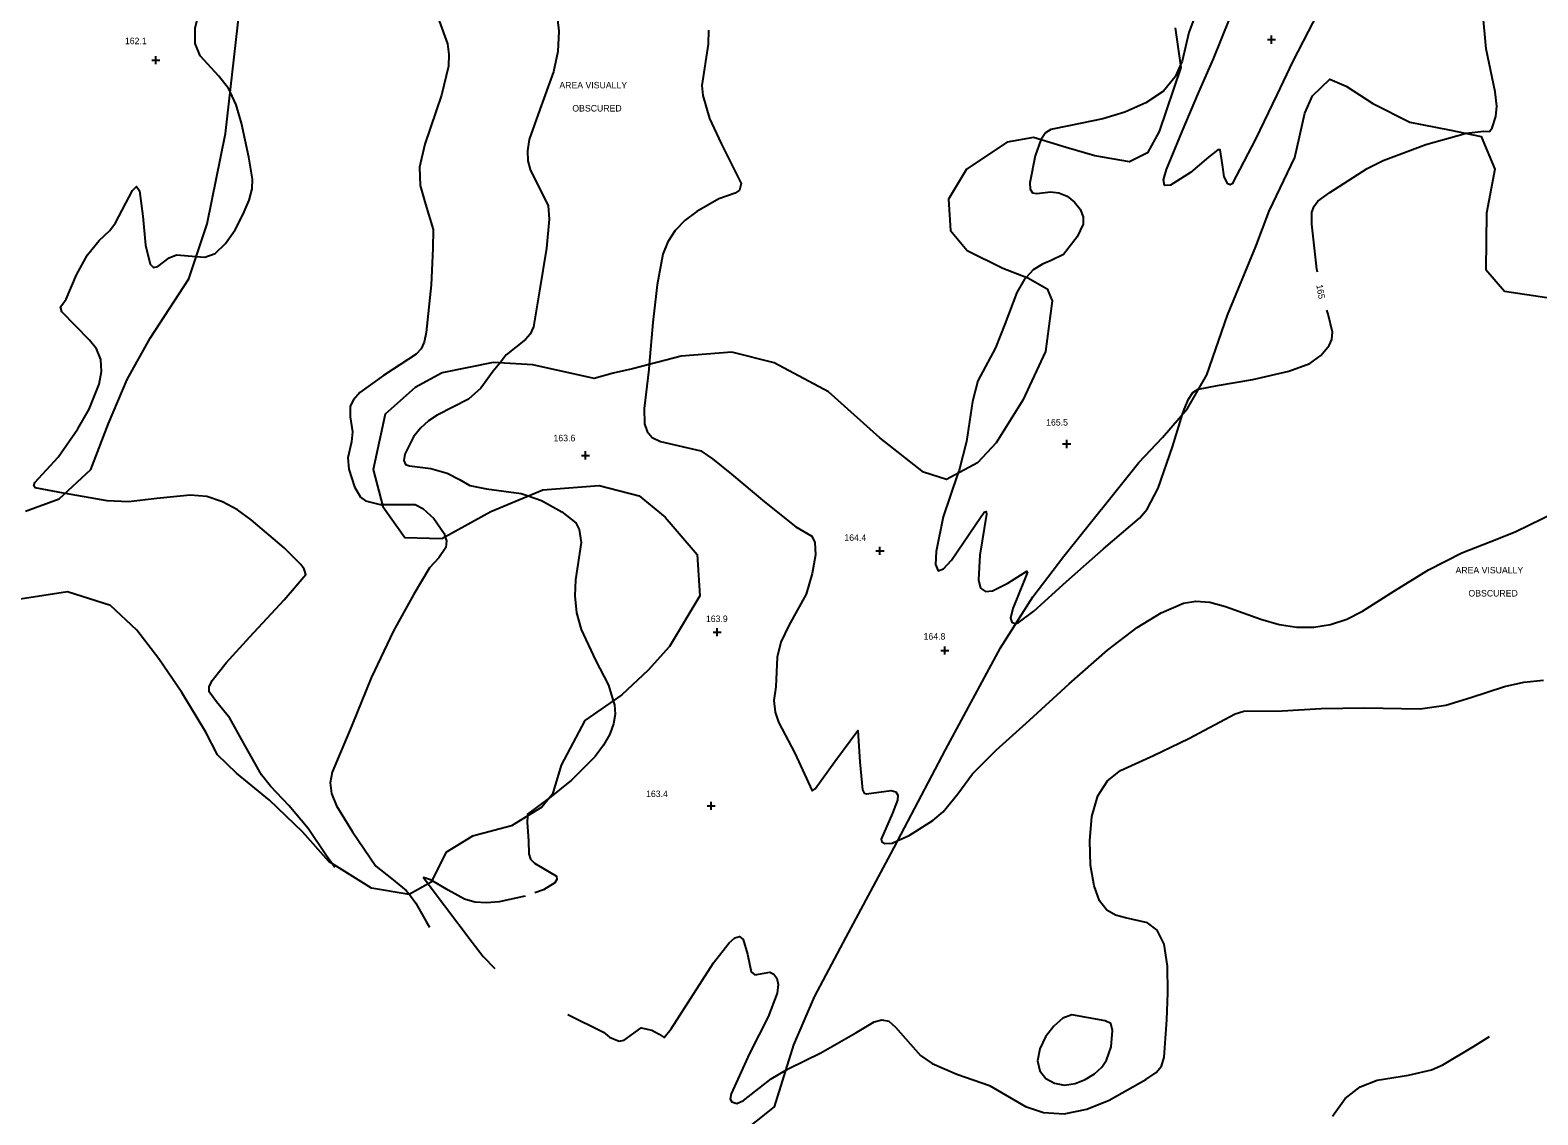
# Model space of a CAD drawing. Extents: x 1467615 to 2003689, y 770235 to 1108726.
# Drawn here: x 1998713.9 to 1999177.2, y 774676.6 to 775010.1 of the extents above; entities that cross this region are included whole.
import ezdxf

# ---------------------------------------------------------------- set-up
doc = ezdxf.new("R2010")
doc.units = 0
for name, color, linetype in [('RD_DTM_Major1', 7, 'Continuous'), ('RD_DTM_Major1_Lbl', 7, 'Continuous'), ('RD_DTM_Major2', 7, 'Continuous'), ('RD_DTM_Minor1', 7, 'Continuous'), ('RD_DTM_Minor2', 7, 'Continuous'), ('RD_DTM_Obscure', 7, 'Continuous'), ('RD_DTM_Spot_Elev', 7, 'Continuous'), ('RD_TX_Misc1', 7, 'Continuous')]:
    doc.layers.add(name, color=color, linetype=linetype)

msp = doc.modelspace()

# ---------------------------------------------------------------- linework, layer by layer
at = {"layer": 'RD_DTM_Major1'}
for points in [[(1999093.32, 775063.9), (1999090.35, 775061.66), (1999087.9, 775058.69), (1999085.26, 775053.24), (1999081.17, 775042.14), (1999078.45, 775030.23), (1999075.47, 775020.42), (1999073.98, 775017.94), (1999072.05, 775015.06), (1999069.94, 775009.38), (1999067.83, 775000.5), (1999067.36, 774999.45)], [(1999113.39, 775022.77), (1999106.54, 775009.68), (1999101.89, 775000.49), (1999096.94, 774990.22), (1999090.36, 774976.51), (1999083.27, 774962.77), (1999082.58, 774962.47), (1999081.93, 774962.81), (1999080.79, 774965), (1999080.22, 774968.68), (1999079.55, 774973.22), (1999078.86, 774973.28), (1999076, 774970.97), (1999070.45, 774966.32), (1999064.25, 774962.39), (1999062.43, 774962.28), (1999062.12, 774964.06), (1999063.01, 774967.27), (1999067.89, 774978.92), (1999072.98, 774990.95), (1999077.52, 775001.22), (1999082.39, 775013.49)], [(1999155.09, 774978.36), (1999160.58, 774979.05), (1999162.26, 774978.93), (1999163.14, 774980.07), (1999164.25, 774983.54), (1999164.6, 774986.68), (1999164.04, 774991.15), (1999161.25, 775004.33), (1999160.29, 775015.45)], [(1999024.48, 774976.37), (1999022.66, 774971.43), (1999021.07, 774963.15), (1999021.19, 774961.21), (1999021.87, 774960.06), (1999023.23, 774959.81), (1999027.44, 774960.33), (1999029.95, 774960.1), (1999032.48, 774959), (1999034.76, 774957.2), (1999036.52, 774954.98), (1999037.48, 774952.64), (1999037.46, 774950.42), (1999035.56, 774946.55), (1999031.37, 774941.09), (1999027.58, 774939.27), (1999024.93, 774938.14), (1999022.12, 774936.34), (1999020.02, 774934.13)], [(1999068.01, 774892.03), (1999068.45, 774893.42), (1999069.79, 774896.65), (1999071.11, 774898.66), (1999072.76, 774899.71), (1999072.91, 774899.74)], [(1998998.97, 774873.79), (1998994.38, 774860.48), (1998992.24, 774849.79), (1998992.1, 774845.79), (1998992.84, 774843.83), (1998994.57, 774844.48), (1998996.97, 774847.13), (1999004.34, 774858.03), (1999007.04, 774861.85), (1999007.63, 774862.13), (1999007.74, 774861.22), (1999005.66, 774848.67), (1999005.25, 774841.03), (1999005.94, 774838.55), (1999007.44, 774837.52), (1999009.54, 774837.7), (1999014.31, 774840.04), (1999020.14, 774843.77), (1999020.32, 774843.38), (1999019.36, 774840.83), (1999015.78, 774832.21), (1999015.1, 774829.24), (1999015.56, 774828.06), (1999016.49, 774827.6), (1999016.78, 774827.68)]]:
    msp.add_lwpolyline(points, dxfattribs=at)
at = {"layer": 'RD_DTM_Major2'}
for points in [[(1999067.36, 774999.45), (1999065.7, 774995.72), (1999062.1, 774991.31), (1999056.72, 774987.68), (1999050.21, 774984.84), (1999043.51, 774982.76), (1999033.01, 774980.63), (1999027.53, 774979.56), (1999025.89, 774978.5), (1999024.59, 774976.68), (1999024.48, 774976.37)], [(1999109.4, 774935.67), (1999109.26, 774936.54), (1999107.67, 774950.4), (1999107.75, 774954.15), (1999108.38, 774955.92), (1999109.54, 774957.44), (1999113.2, 774960.17), (1999124.72, 774967.58), (1999129.66, 774969.96), (1999142.75, 774974.87), (1999154.78, 774978.32), (1999155.09, 774978.36)], [(1999020.02, 774934.13), (1999019.42, 774933.5), (1999017.08, 774929.4), (1999013.34, 774919.66), (1999010.52, 774912.39), (1999005.05, 774902.28), (1999003.4, 774895.9), (1999001.63, 774883.61), (1998999.32, 774874.82), (1998998.97, 774873.79)], [(1999072.91, 774899.74), (1999078.77, 774900.77), (1999089.62, 774902.68), (1999100.65, 774905.2), (1999107.09, 774907.55), (1999110.46, 774910), (1999113.06, 774913.07), (1999113.87, 774914.98), (1999114.1, 774917.21), (1999112.69, 774922.71), (1999112.27, 774923.99)], [(1999016.78, 774827.68), (1999017.42, 774827.86), (1999022.25, 774831.47), (1999032.36, 774840.53), (1999043.71, 774850.64), (1999054.79, 774860.07), (1999057.09, 774862.8), (1999060.44, 774869.22), (1999064.88, 774882.01), (1999068.01, 774892.03)]]:
    msp.add_lwpolyline(points, dxfattribs=at)
at = {"layer": 'RD_DTM_Minor1'}
msp.add_line((1998807.45, 774752.68), (1998806.52, 774754), dxfattribs=at)
for points in [[(1998775.28, 774991.06), (1998774.8, 774992.1), (1998771.85, 774995.95), (1998766.13, 775002.21), (1998764.57, 775005.92), (1998764.52, 775010.63), (1998765.76, 775015.76), (1998767.9, 775020.49), (1998770.54, 775024.01), (1998773.35, 775025.76), (1998779.41, 775027.42)], [(1998724.59, 774867.63), (1998715.44, 774869.35), (1998714.94, 774870), (1998715.32, 774870.96), (1998722.45, 774878.8), (1998728.54, 774887.53), (1998731.98, 774893.58), (1998735.04, 774901.21), (1998735.77, 774905.14), (1998735.56, 774908.83), (1998734.21, 774912.05), (1998732.09, 774914.79), (1998723.61, 774923.51), (1998723.2, 774925.03), (1998723.92, 774925.88), (1998724.95, 774927.4), (1998728.1, 774934.88), (1998731.5, 774941.03), (1998735.04, 774945.36), (1998738.37, 774948.43), (1998740.09, 774950.81), (1998745.28, 774960.81), (1998746.58, 774961.96), (1998747.46, 774960.62), (1998748.44, 774952.9), (1998749.3, 774943.94), (1998750.76, 774938.13), (1998751.8, 774937.07), (1998753.1, 774937.44), (1998756.59, 774940.09), (1998758.85, 774940.96), (1998764.9, 774940.47)], [(1998858.16, 774907.73), (1998856.18, 774905.18), (1998852.39, 774899.98), (1998848.55, 774896.65), (1998838.89, 774891.69), (1998836.24, 774889.92), (1998833.77, 774887.72), (1998831.64, 774885.08), (1998828.95, 774879.71), (1998828.65, 774877.72), (1998829.17, 774876.58), (1998830.42, 774876.09), (1998836.96, 774875.33), (1998841.98, 774873.82), (1998845.81, 774871.89), (1998849.01, 774870.1), (1998854.07, 774869.01), (1998864.74, 774867.64), (1998866.91, 774866.89)], [(1998904.11, 774907.28), (1998903.97, 774905.76), (1998902.54, 774893.71), (1998902.67, 774889.04), (1998903.45, 774886.7), (1998905.04, 774884.81), (1998907.6, 774883.6), (1998919.94, 774880.69), (1998923.51, 774878.24), (1998929.35, 774873.53), (1998939.48, 774865.04), (1998949.1, 774857.38), (1998954.1, 774854.51), (1998954.97, 774852.53), (1998955.17, 774848.73), (1998954.18, 774843.04), (1998952.36, 774836.69), (1998947, 774827), (1998944.5, 774821.91), (1998943.44, 774817.29), (1998942.99, 774808.22), (1998942.43, 774804.01), (1998942.76, 774800.43), (1998943.81, 774797.31), (1998948.82, 774787.78), (1998954.19, 774776.21), (1998955.04, 774776.82), (1998961.1, 774785.2), (1998968.19, 774794.8), (1998968.85, 774785.15), (1998969.68, 774776.48), (1998970.11, 774775.5), (1998970.88, 774775.24), (1998978.39, 774776.27), (1998979.9, 774775.89), (1998980.53, 774774.88), (1998980.41, 774773.34), (1998978.84, 774769.38), (1998975.32, 774761.37), (1998975.58, 774760.48), (1998976.48, 774759.98), (1998978.72, 774760.14), (1998980.49, 774760.93)], [(1998822.11, 774864.24), (1998827.69, 774864.23), (1998832.16, 774864.23), (1998834.57, 774863.05), (1998837.9, 774859.94), (1998841.08, 774855.34), (1998841.39, 774854.32)], [(1998893.06, 774803.92), (1998893.47, 774802.63), (1998893.58, 774799.76), (1998893.09, 774796.77), (1998891.95, 774793.62), (1998890.09, 774790.29), (1998887.46, 774786.77), (1998880.26, 774779.52), (1998873.38, 774773.97)], [(1998866.67, 774768.45), (1998866.6, 774766.45), (1998866.96, 774760.79), (1998867.08, 774756.79), (1998867.66, 774755.17), (1998868.8, 774753.96), (1998875.55, 774749.94), (1998875.71, 774748.97), (1998875.12, 774747.93), (1998871.57, 774745.78), (1998868.99, 774744.89)], [(1998836.15, 774747.59), (1998841.21, 774740.95), (1998849.7, 774729.73), (1998853.08, 774725.3), (1998856.69, 774721.6)], [(1998865.94, 774743.85), (1998865.49, 774743.69), (1998857.94, 774742.07), (1998854.1, 774741.76), (1998850.5, 774742), (1998847.32, 774742.89), (1998842.28, 774745.63), (1998837.33, 774748.61)], [(1998830.39, 774744.32), (1998832.42, 774741.72), (1998835.7, 774735.83), (1998836.57, 774734.3)], [(1998879.12, 774707.45), (1998879.13, 774707.44), (1998890.02, 774701.96), (1998891.85, 774700.52), (1998894.9, 774699.27), (1998896.4, 774699.59), (1998901.58, 774703.32), (1998904.85, 774702.66), (1998907.18, 774701.35), (1998908.67, 774700.35), (1998910.8, 774703.03), (1998916.84, 774712.46), (1998923.86, 774723.3), (1998928.64, 774729.5), (1998930.37, 774731.03), (1998931.86, 774731.45), (1998932.97, 774730.46), (1998934.28, 774725.94), (1998935.37, 774720.53), (1998936.54, 774719.67), (1998941.15, 774720.41), (1998942.35, 774719.82), (1998943.27, 774718.6), (1998943.7, 774716.69), (1998943.43, 774714.03), (1998940.6, 774706.71), (1998934.89, 774695.41), (1998929.24, 774683.06), (1998928.96, 774681.39), (1998929.47, 774680.61), (1998930.99, 774680.06), (1998933.08, 774681.01), (1998941.56, 774687.7), (1998946.12, 774690.3)]]:
    msp.add_lwpolyline(points, dxfattribs=at)
at = {"layer": 'RD_DTM_Minor2'}
for points in [[(1998875.57, 775015.98), (1998876.32, 775009.78), (1998876.01, 775003.46), (1998874.66, 774997.2), (1998870.46, 774985.63), (1998867.25, 774976.49), (1998866.67, 774972.96), (1998866.77, 774969.93), (1998867.52, 774967.26), (1998872.99, 774956.06), (1998873.34, 774951.98), (1998872.54, 774943), (1998870.34, 774929.92), (1998868.52, 774918.9), (1998867.5, 774916.63), (1998866.04, 774914.91), (1998860.14, 774910.28), (1998858.16, 774907.73)], [(1998839.55, 775012.95), (1998842.09, 775005.86), (1998842.53, 775002.56), (1998842.38, 774999.03), (1998840.23, 774990.11), (1998835.18, 774974.98), (1998833.54, 774967.91), (1998833.75, 774962.31), (1998835.36, 774956.54), (1998837.73, 774948.73), (1998837.64, 774942.98), (1998837.04, 774931.76), (1998835.6, 774917.11), (1998834.98, 774914.1), (1998834.04, 774912.05), (1998832.48, 774910.43), (1998822.4, 774903.9), (1998815.17, 774898.64), (1998813.18, 774896.42), (1998812.24, 774894.5), (1998812.24, 774891.2), (1998812.93, 774886.56), (1998812.57, 774883.45), (1998811.47, 774878.57), (1998811.81, 774875.09), (1998813.5, 774869.67), (1998815.4, 774866.49), (1998816.95, 774865.34), (1998821.39, 774864.24), (1998822.11, 774864.24)], [(1998922.27, 775010.11), (1998922.18, 775005.78), (1998920.27, 774993.03), (1998920.53, 774990.01), (1998922.62, 774982.94), (1998926.19, 774975.21), (1998932.38, 774962.91), (1998931.85, 774960.91), (1998930.53, 774959.92), (1998925.52, 774958.19), (1998918.74, 774954.36), (1998915.14, 774951.62), (1998912.04, 774948.48), (1998909.78, 774945.02), (1998908.27, 774941.15), (1998906.51, 774931.74), (1998905.25, 774920.15), (1998904.11, 774907.28)], [(1998764.9, 774940.47), (1998767.49, 774940.25), (1998770.7, 774941.43), (1998773.9, 774944.43), (1998776.86, 774948.71), (1998779.36, 774953.46), (1998781.15, 774957.84), (1998782.06, 774961.3), (1998782.23, 774964.22), (1998781.09, 774970.99), (1998778.85, 774981.51), (1998777.13, 774987.14), (1998775.28, 774991.06)], [(1998806.52, 774754), (1998804.97, 774756.23), (1998799.29, 774764.61), (1998793.34, 774771.74), (1998787.68, 774777.62), (1998784.99, 774781.1), (1998779.89, 774790.06), (1998775.18, 774798.58), (1998771.09, 774803.6), (1998768.87, 774806.64), (1998768.91, 774808.2), (1998769.79, 774810.09), (1998774.13, 774815.52), (1998781.39, 774823.54), (1998791.94, 774834.95), (1998798.61, 774842.76), (1998798.08, 774844.4), (1998797.05, 774845.82), (1998791.89, 774850.88), (1998781.81, 774859.57), (1998777.59, 774862.58), (1998773.01, 774865.08), (1998768.12, 774866.69), (1998763, 774867.15), (1998752.8, 774866.03), (1998744.06, 774865.04), (1998737.55, 774865.38), (1998724.69, 774867.62), (1998724.59, 774867.63)], [(1998866.91, 774866.89), (1998870.95, 774865.48), (1998877.25, 774861.94), (1998881.51, 774858.59), (1998882.55, 774856.5), (1998883.16, 774852.54), (1998881.4, 774841.08), (1998881.2, 774836.15), (1998881.71, 774830.97), (1998883.14, 774825.83), (1998887.57, 774816.33), (1998891.55, 774808.67), (1998893.06, 774803.92)], [(1998980.49, 774760.93), (1998983.96, 774762.49), (1998991.21, 774767.08), (1998994.44, 774769.76), (1998998.96, 774775.29), (1999003.43, 774781.41), (1999010.71, 774788.71), (1999020.93, 774797.91), (1999033.13, 774809.05), (1999044.87, 774819.42), (1999054.04, 774826.46), (1999061.37, 774830.95), (1999068.29, 774833.94), (1999072.07, 774834.53), (1999076.33, 774834.22), (1999081.19, 774832.91), (1999092.06, 774828.95), (1999097.64, 774827.31), (1999103.08, 774826.47), (1999108.35, 774826.49), (1999113.47, 774827.35), (1999118.45, 774829.02), (1999123.32, 774831.45), (1999133.09, 774837.67), (1999143.52, 774844.11), (1999153.78, 774849.36), (1999164.53, 774853.58), (1999170.44, 774855.91), (1999182.55, 774861.83)], [(1998841.39, 774854.32), (1998841.78, 774853.04), (1998841.55, 774851.01), (1998839.41, 774847.87), (1998836.61, 774844.8), (1998831.75, 774836.65), (1998825.48, 774825.35), (1998818.7, 774810.9), (1998812.72, 774796.29), (1998806.69, 774781.9), (1998806.07, 774778.67), (1998806.49, 774775.36), (1998808.04, 774771.55), (1998812.88, 774763.57), (1998820.12, 774753.02), (1998824.9, 774749.3), (1998829.4, 774745.6), (1998830.39, 774744.32)], [(1998946.12, 774690.3), (1998946.99, 774690.79), (1998956.87, 774695.7), (1998967.59, 774701.85), (1998973.19, 774705.18), (1998975.53, 774705.83), (1998977.7, 774705.36), (1998979.79, 774703.58), (1998987.46, 774694.81), (1998991.03, 774692.38), (1998998.64, 774689.11), (1999008.64, 774685.6), (1999019.73, 774679.16), (1999025.27, 774677.32), (1999031.6, 774676.88), (1999038.52, 774678.34), (1999045.46, 774681.15), (1999056.69, 774687.45), (1999059.83, 774689.59), (1999061.51, 774691.56), (1999062.29, 774694.33), (1999063.18, 774705.82), (1999063.5, 774714.1), (1999063.31, 774722.33), (1999062.28, 774729.1), (1999060.16, 774733.39), (1999057.23, 774735.61), (1999050.47, 774737.11), (1999047.36, 774737.94), (1999044.67, 774739.56), (1999042.45, 774742.42), (1999040.77, 774746.95), (1999039.72, 774753.34), (1999039.45, 774760.8), (1999040.12, 774768.27), (1999041.91, 774774.7), (1999044.91, 774779.31), (1999048.94, 774782.48), (1999059.01, 774787.05), (1999069.9, 774792.33), (1999084.16, 774799.86), (1999086.77, 774800.67), (1999098.56, 774800.79), (1999110.57, 774801.53), (1999123.9, 774801.7), (1999141.04, 774801.43), (1999148.85, 774802.49), (1999156.55, 774804.94), (1999166.96, 774808.32), (1999172.87, 774809.63), (1999178.91, 774810.21)], [(1998873.38, 774773.97), (1998873.07, 774773.71), (1998866.69, 774769.06), (1998866.67, 774768.45)], [(1998837.33, 774748.61), (1998836.9, 774748.87), (1998834.69, 774749.51), (1998836.15, 774747.59)], [(1999031.71, 774685.75), (1999034.96, 774686.2), (1999038.09, 774687.45), (1999040.9, 774689.23), (1999043.13, 774691.3), (1999044.64, 774693.41), (1999046.03, 774697.5), (1999046.48, 774702.56), (1999045.95, 774704.65), (1999044.19, 774705.53), (1999033.97, 774707.37), (1999031.21, 774706.28), (1999028.4, 774703.9), (1999025.91, 774700.58), (1999024.12, 774696.84), (1999023.43, 774693.2), (1999024.12, 774690.13), (1999025.95, 774687.79), (1999028.6, 774686.29), (1999031.71, 774685.75)], [(1999114.1, 774676.23), (1999117.93, 774681.65), (1999122.61, 774685.22), (1999127.75, 774687.24), (1999137.44, 774688.84), (1999144.52, 774690.39), (1999147.99, 774691.92), (1999157.43, 774697.6), (1999162.33, 774700.68)]]:
    msp.add_lwpolyline(points, dxfattribs=at)
at = {"layer": 'RD_DTM_Obscure'}
for points in [[(1998712.46, 774862.18), (1998722.8, 774865.97), (1998732.5, 774874.97), (1998737.91, 774889.18), (1998743.65, 774902.62), (1998750.7, 774915.4), (1998762.65, 774933.65), (1998768.22, 774950.54), (1998773.84, 774978.33), (1998779.68, 775029.84)], [(1999065.7, 775010.77), (1999067.49, 774998.6), (1999060.79, 774978.87), (1999057.16, 774972.38), (1999051.64, 774969.63), (1999041.02, 774971.39), (1999032.17, 774974.01), (1999022.2, 774977.07), (1999014.09, 774975.63), (1999001.56, 774967.36), (1998996.05, 774958.12), (1998996.65, 774948.52), (1999001.83, 774942.3), (1999012.8, 774936.88), (1999020.48, 774933.95), (1999026.41, 774930.55), (1999027.91, 774926.83), (1999025.87, 774911.25), (1999018.88, 774896.35), (1999010.66, 774883.24), (1999004.95, 774877.07), (1998995.47, 774871.87), (1998988.33, 774874.2), (1998974.97, 774884.72), (1998959.15, 774898.83), (1998942.46, 774907.82), (1998929.47, 774911.06), (1998913.93, 774909.85), (1998898.99, 774905.94), (1998893, 774904.57), (1998887.18, 774903), (1998868.32, 774907.14), (1998856.14, 774907.84), (1998840.49, 774904.74), (1998832.21, 774900.25), (1998822.96, 774892), (1998819.3, 774875.04), (1998822.27, 774863.6), (1998828.97, 774854.05), (1998840.41, 774853.77), (1998855.4, 774862.07), (1998871.45, 774868.79), (1998888.72, 774870.08), (1998900.96, 774866.89), (1998909, 774860.31), (1998918.86, 774848.83), (1998919.66, 774836.15), (1998910.34, 774820.61), (1998903.79, 774813.33), (1998895.7, 774805.76), (1998884.33, 774797.81), (1998877.03, 774784.07), (1998874.42, 774775.23), (1998871.13, 774771.22), (1998861.81, 774765.44), (1998849.77, 774762.31), (1998841.63, 774757.24), (1998837.09, 774748.12), (1998830.36, 774744.3), (1998818.8, 774746.31), (1998805.69, 774754.53), (1998797.6, 774763.6), (1998787.45, 774773.37), (1998777.22, 774781.61), (1998771.43, 774787.3), (1998767.81, 774794.2), (1998760.49, 774806.48), (1998753.43, 774816.83), (1998746.68, 774825.63), (1998738.51, 774833.17), (1998725.38, 774837.37), (1998710.75, 774835.16)], [(1998932.01, 774670.69), (1998942.64, 774679.07), (1998948.53, 774698.07), (1998954.93, 774712.83), (1998964.61, 774731.22), (1998978.34, 774756.85), (1998995.12, 774788.8), (1999012.04, 774820.16), (1999021.94, 774835.85), (1999031.45, 774848.3), (1999054.54, 774877.18), (1999061.86, 774884.79), (1999069.45, 774893.72), (1999075.41, 774904.09), (1999081.83, 774922.47), (1999090.5, 774943.58), (1999094.58, 774954.44), (1999102.51, 774970.92), (1999105.59, 774984.52), (1999107.91, 774989.84), (1999113.28, 774994.98), (1999118.23, 774992.88), (1999126.43, 774987.52), (1999137.87, 774981.79), (1999149.89, 774979.47), (1999159.72, 774977.37), (1999163.93, 774967.37), (1999161.33, 774953.83), (1999161.19, 774936.51), (1999166.93, 774929.86), (1999179.94, 774927.86)]]:
    msp.add_lwpolyline(points, dxfattribs=at)
at = {"layer": 'RD_DTM_Spot_Elev'}
for p, q in [((1999094.08, 775007.14), (1999096.58, 775007.14)), ((1999095.33, 775005.89), (1999095.33, 775008.39)), ((1998751.25, 775000.85), (1998753.75, 775000.85)), ((1998752.5, 774999.6), (1998752.5, 775002.1)), ((1999032.38, 774881.59), (1999032.38, 774884.09)), ((1998884.54, 774878.08), (1998884.54, 774880.58)), ((1999031.13, 774882.84), (1999033.63, 774882.84)), ((1998883.29, 774879.33), (1998885.79, 774879.33)), ((1998973.75, 774850), (1998976.25, 774850)), ((1998975, 774848.75), (1998975, 774851.25)), ((1998923.75, 774825), (1998926.25, 774825)), ((1998925, 774823.75), (1998925, 774826.25)), ((1998993.7, 774819.33), (1998996.2, 774819.33)), ((1998994.95, 774818.08), (1998994.95, 774820.58)), ((1998921.88, 774771.61), (1998924.38, 774771.61)), ((1998923.13, 774770.36), (1998923.13, 774772.86))]:
    msp.add_line(p, q, dxfattribs=at)

# ---------------------------------------------------------------- texts
at = {"layer": 'RD_DTM_Major1_Lbl'}
msp.add_text('165', height=2, rotation=279.6949, dxfattribs=at).set_placement((1999109.07, 774931.69))
at = {"layer": 'RD_DTM_Spot_Elev'}
for s, p in [('162.1', (1998742.98, 775005.75)), ('165.5', (1999026.07, 774888.49)), ('163.6', (1998874.69, 774883.67)), ('164.4', (1998964.06, 774853.05)), ('163.9', (1998921.51, 774828.1)), ('164.8', (1998988.4, 774822.69)), ('163.4', (1998903.13, 774774.29))]:
    msp.add_text(s, height=2, dxfattribs=at).set_placement(p)
at = {"layer": 'RD_TX_Misc1'}
for s, p in [('AREA VISUALLY', (1998876.49, 774992.16)), ('OBSCURED', (1998880.47, 774985.05)), ('AREA VISUALLY', (1999151.86, 774843.05)), ('OBSCURED', (1999155.84, 774835.94))]:
    msp.add_text(s, height=2, dxfattribs=at).set_placement(p)

doc.saveas('drawing.dxf')
